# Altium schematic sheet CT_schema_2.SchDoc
size 294 x 169 mm
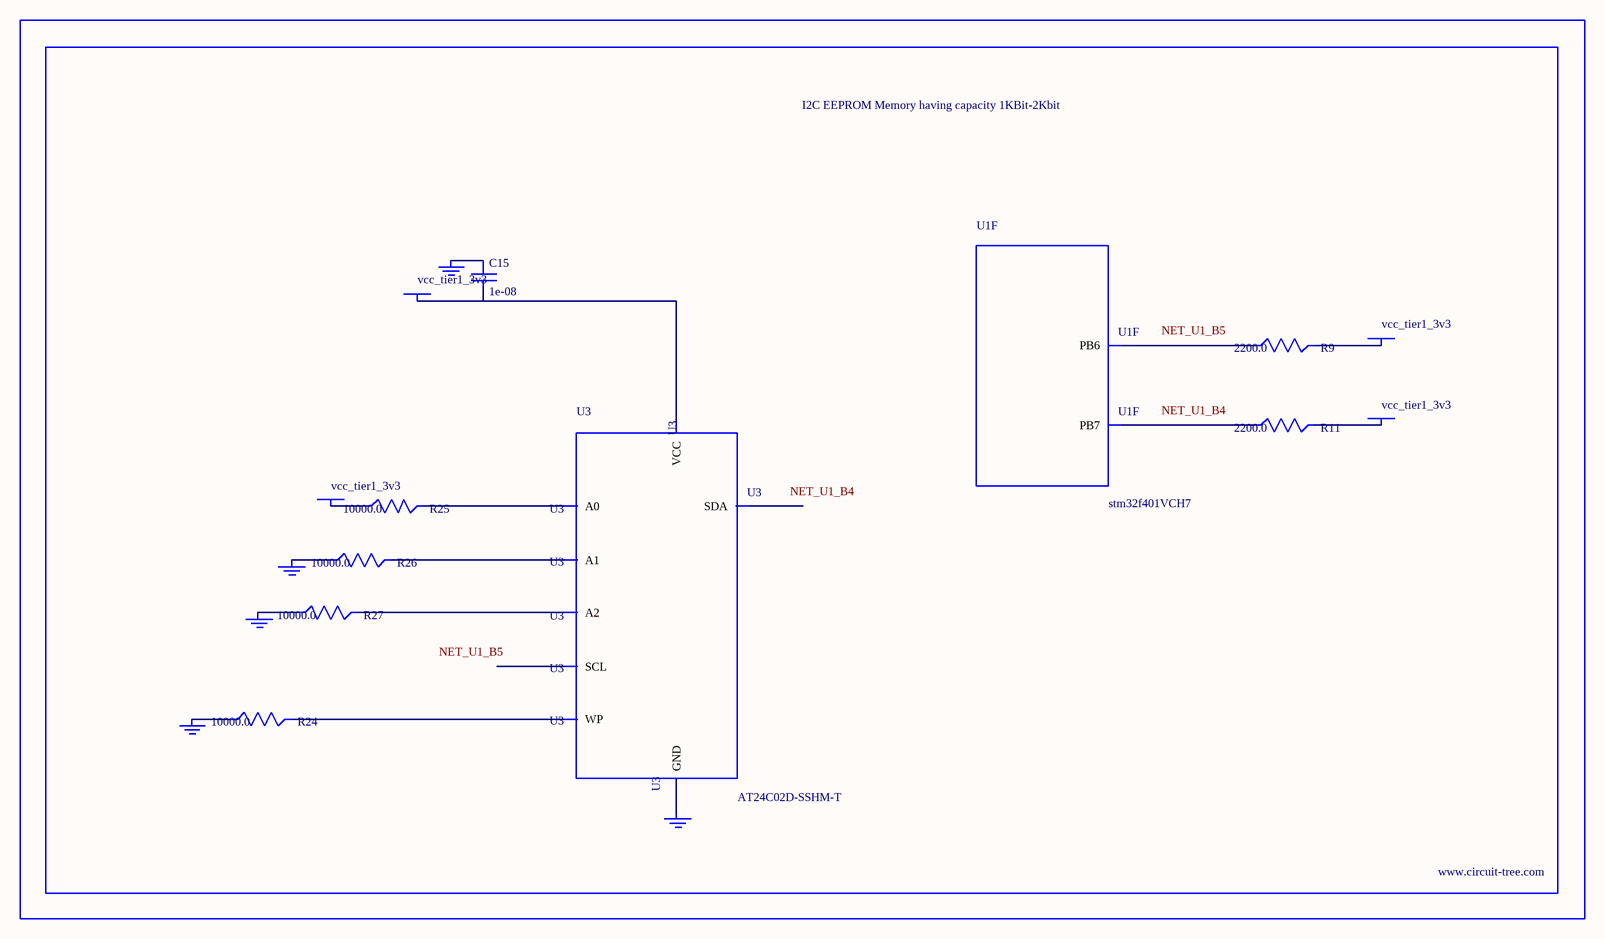
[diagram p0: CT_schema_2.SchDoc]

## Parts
BORDER1  (no value)
C15  1e-08  [C0402]
GND_INSTANCE_1_0  (no value)
GND_INSTANCE_1_1  (no value)
GND_INSTANCE_1_2  (no value)
GND_INSTANCE_1_3  (no value)
GND_INSTANCE_1_4  (no value)
POWER_INSTANCE_1_0  vcc_tier1_3v3
POWER_INSTANCE_1_1  vcc_tier1_3v3
POWER_INSTANCE_1_2  vcc_tier1_3v3
POWER_INSTANCE_1_3  vcc_tier1_3v3
R9  2200.0  [R0603]
R11  2200.0  [R0603]
R24  10000.0  [R0603]
R25  10000.0  [R0603]
R26  10000.0  [R0603]
R27  10000.0  [R0603]
U1  stm32f401VCH7  [UFBGA100]  (part F of 10)
U3  AT24C02D-SSHM-T  [AT24C02D]

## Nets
NetC15_1: C15.1 GND_INSTANCE_1_3.0(GND)
NetC15_2: C15.2 POWER_INSTANCE_1_1.0(PWR) U3.8(VCC)
NetGND_INSTANCE_1_0_0: GND_INSTANCE_1_0.0(GND) R26.1
NetGND_INSTANCE_1_1_0: GND_INSTANCE_1_1.0(GND) R27.1
NetGND_INSTANCE_1_2_0: GND_INSTANCE_1_2.0(GND) R24.1
NetGND_INSTANCE_1_4_0: GND_INSTANCE_1_4.0(GND) U3.4(GND)
NetPOWER_INSTANCE_1_0_0: POWER_INSTANCE_1_0.0(PWR) R25.1
NetPOWER_INSTANCE_1_2_0: POWER_INSTANCE_1_2.0(PWR) R9.2
NetPOWER_INSTANCE_1_3_0: POWER_INSTANCE_1_3.0(PWR) R11.2
NetR9_1: R9.1 U1.B5(PB6)
NetR11_1: R11.1 U1.B4(PB7)
NetR24_2: R24.2 U3.7(WP)
NetR25_2: R25.2 U3.1(A0)
NetR26_2: R26.2 U3.2(A1)
NetR27_2: R27.2 U3.3(A2)

Not connected (* = marked no-connect by the designer): U3 5(SDA) 6(SCL)

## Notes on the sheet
- Labels drawn without touching a wire or pin: NET_U1_B4, NET_U1_B5

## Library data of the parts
BORDER1 = BORDER_PAGE1
C15 = C0402C103K3RAC
GND_INSTANCE_1_0-GND_INSTANCE_1_4 = GND
POWER_INSTANCE_1_0-POWER_INSTANCE_1_3 = PWR
R9 R11 = RC0603JR-072K2L
R24-R27 = RC0603JR-0710KL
